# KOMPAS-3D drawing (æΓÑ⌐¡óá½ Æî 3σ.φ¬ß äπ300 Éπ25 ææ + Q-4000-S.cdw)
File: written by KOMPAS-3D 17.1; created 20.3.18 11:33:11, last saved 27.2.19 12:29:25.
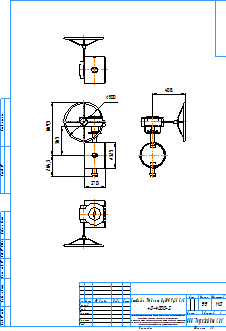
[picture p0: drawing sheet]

Sheet 1: A3, portrait

Title block, sheet 1: name: Стейнвал ТМ 3х.экс Ду300 Ру25 С/С / + Q-4000-S; mass: 99; sheets: 1; sheet format: A3; stored path: C:\Users\kka\KOMPAS_Work\Дисковые повортные затворы ф. Boteli\Стейнвал + редуктор-привода\Стейнвал ТМ 3х.экс Ду300 Ру25 СС + Q-4000-S.cdw

Views: Вид 1, Проекционный вид 2, Проекционный вид 3, Проекционный вид 4
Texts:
  kka
  adl
  Рама для чертежей
  Лит-Масса-Масштаб
  Материал-Предприятие
  Масштаб
  Изм.
  Лист
  № докум.
  Подп.
  Дата
  Лит.
  Разраб.
  Пров.
  Т.контр.
  Листов
  Внимание! Данный продукт является объектом авторского права ООО «Торговый Дом АДЛ».
  Запрещается изменение, копирование, распространение
  (в том числе путем копирования на другие сайты и ресурсы в Интернете)
  или любое иное использование информации и объектов без предварительного
  согласия правообладателя (ООО «Торговый Дом АДЛ»).
  Н.контр.
  Утв.
  ООО "Торговый дом АДЛ"
  Изменение
  Номер документа
  Подпись
  Обозначение документа
  Наименование изделия
  Масса изделия по ГОСТ 2.109-73
  Порядковый номер листа
  Общее количество листов в документе
  Характер работы, выполненной лицом, подписавшим документ
  Наименование или индекс предприятия, выпускающего документ
  Инв. № подл.
  Подп. и дата
  Взам. инв. №
  Инв. № дубл.
  Инвентарный номер подлинника по ГОСТ 2.501-68
  Подпись принявшего подлинник в отдел технической документации
  Инвентарный номер подлинника, взамен которого выпущен данный подлинник
  Инвентарный номер дубликата по ГОСТ 2.502-68
  Подпись принявшего дубликат в отдел технической документации
  Справ. №
  Перв. примен.
  Обозначение документа, взамен или на основании которого выпущен данный документ
  Обозначение документа, в котором впервые записан данный документ
  Подпись лица, копировавшего чертеж
  Обозначение формата листа
  !Рама для чертежа
Dimensions and other numbers on the sheet: 270; 669,5; 264,3; 325; 500; 365; 408; 1:10; 1; 99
